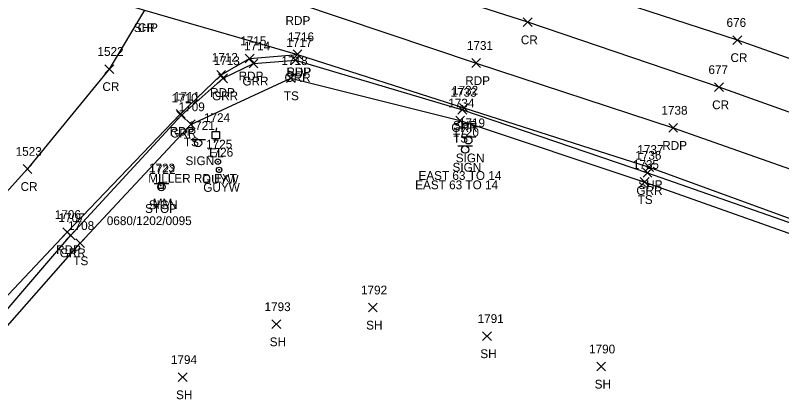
# Model space of a CAD drawing. Extents: x 1629176 to 1637209, y 606063 to 610167.
# Drawn here: x 1629900.9 to 1630075.4, y 606839.8 to 606927.3 of the extents above; entities that cross this region are included whole.
import ezdxf

# ---------------------------------------------------------------- set-up
doc = ezdxf.new("R2010")
doc.units = 0
for name, color, linetype in [('L_A', 7, 'Continuous'), ('L_I', 7, 'Continuous'), ('L_TIC', 7, 'Continuous'), ('LELB', 7, 'Continuous'), ('P_A', 7, 'Continuous'), ('P_I', 7, 'Continuous'), ('P_TIC', 7, 'Continuous'), ('PET', 7, 'Continuous'), ('PRC', 7, 'Continuous'), ('PSP', 7, 'Continuous'), ('R_A', 7, 'Continuous'), ('R_I', 7, 'Continuous'), ('R_TIC', 7, 'Continuous'), ('RGR', 7, 'Continuous'), ('S_A', 7, 'Continuous'), ('S_C', 7, 'Continuous'), ('S_I', 7, 'Continuous'), ('SRM', 7, 'Continuous'), ('SSGN', 7, 'Continuous'), ('U_A', 7, 'Continuous'), ('U_I', 7, 'Continuous'), ('UEPT', 7, 'Continuous'), ('UPGW', 7, 'Continuous')]:
    doc.layers.add(name, color=color, linetype=linetype)

msp = doc.modelspace()

# ---------------------------------------------------------------- linework, layer by layer
at = {"layer": 'L_TIC'}
for points in [[(1629962.67, 606911.99), (1629964.67, 606913.99)], [(1629964.67, 606911.99), (1629962.67, 606913.99)], [(1629939.9, 606901.48), (1629941.9, 606903.48)], [(1629941.9, 606901.48), (1629939.9, 606903.48)], [(1630001.21, 606902.33), (1630003.21, 606904.33)], [(1630003.21, 606902.33), (1630001.21, 606904.33)], [(1630043.25, 606888.35), (1630045.25, 606890.35)], [(1630045.25, 606888.35), (1630043.25, 606890.35)], [(1629914.71, 606874.42), (1629916.71, 606876.42)], [(1629916.71, 606874.42), (1629914.71, 606876.42)], [(1629981.34, 606859.75), (1629983.34, 606861.75)], [(1629983.34, 606859.75), (1629981.34, 606861.75)], [(1629959.37, 606855.95), (1629961.37, 606857.95)], [(1629961.37, 606855.95), (1629959.37, 606857.95)], [(1630007.33, 606853.24), (1630009.33, 606855.24)], [(1630009.33, 606853.24), (1630007.33, 606855.24)], [(1630033.36, 606846.31), (1630035.36, 606848.31)], [(1630035.36, 606846.31), (1630033.36, 606848.31)], [(1629938.04, 606843.89), (1629940.04, 606845.89)], [(1629940.04, 606843.89), (1629938.04, 606845.89)]]:
    msp.add_lwpolyline(points, dxfattribs=at)
at = {"layer": 'LELB'}
msp.add_lwpolyline([(1630072.99, 606627.47), (1630041.99, 606654.51), (1630010.01, 606681.22), (1629981.64, 606706.28), (1629935.83, 606746.98), (1629900.42, 606776.48), (1629884.89, 606790.02), (1629879.22, 606802.61), (1629877.3, 606811.37), (1629877.5, 606819.88), (1629880.93, 606830.79), (1629891.36, 606847.82), (1629915.71, 606875.42), (1629940.9, 606902.48), (1629963.67, 606912.99), (1630002.21, 606903.33), (1630044.25, 606889.35), (1630091.41, 606872.59)], dxfattribs=at)
at = {"layer": 'P_TIC'}
for points in [[(1630016.61, 606924.74), (1630018.61, 606926.74)], [(1630018.61, 606924.74), (1630016.61, 606926.74)], [(1630064.36, 606920.68), (1630066.36, 606922.68)], [(1630066.36, 606920.68), (1630064.36, 606922.68)], [(1629953.28, 606916.5), (1629955.28, 606918.5)], [(1629955.28, 606916.5), (1629953.28, 606918.5)], [(1629964.2, 606917.43), (1629966.2, 606919.43)], [(1629966.2, 606917.43), (1629964.2, 606919.43)], [(1629964.2, 606917.43), (1629966.2, 606919.43)], [(1629966.2, 606917.43), (1629964.2, 606919.43)], [(1630004.89, 606915.45), (1630006.89, 606917.45)], [(1630006.89, 606915.45), (1630004.89, 606917.45)], [(1629921.33, 606914.08), (1629923.33, 606916.08)], [(1629923.33, 606914.08), (1629921.33, 606916.08)], [(1629946.79, 606912.74), (1629948.79, 606914.74)], [(1629948.79, 606912.74), (1629946.79, 606914.74)], [(1630060.18, 606909.94), (1630062.18, 606911.94)], [(1630062.18, 606909.94), (1630060.18, 606911.94)], [(1630002.07, 606905.25), (1630004.07, 606907.25)], [(1630004.07, 606905.25), (1630002.07, 606907.25)], [(1629937.57, 606903.89), (1629939.57, 606905.89)], [(1629939.57, 606903.89), (1629937.57, 606905.89)], [(1630049.76, 606900.68), (1630051.76, 606902.68)], [(1630051.76, 606900.68), (1630049.76, 606902.68)], [(1629902.69, 606891.32), (1629904.69, 606893.32)], [(1629904.69, 606891.32), (1629902.69, 606893.32)], [(1630044.28, 606891.75), (1630046.28, 606893.75)], [(1630046.28, 606891.75), (1630044.28, 606893.75)], [(1629911.73, 606876.94), (1629913.73, 606878.94)], [(1629913.73, 606876.94), (1629911.73, 606878.94)]]:
    msp.add_lwpolyline(points, dxfattribs=at)
at = {"layer": 'PET'}
for points in [[(1629181.97, 607055.08), (1629220.58, 607054.17), (1629264.89, 607052.3), (1629300.55, 607050.62), (1629344.63, 607047.49), (1629382.7, 607044.36), (1629427.5, 607039.91), (1629466.96, 607035.43), (1629507.21, 607030.19), (1629538.75, 607025.9), (1629578.99, 607019.69), (1629624.23, 607012.05), (1629673.21, 607003.11), (1629718.04, 606993.87), (1629764.48, 606983.46), (1629805.04, 606973.93), (1629842.82, 606964.4), (1629884.8, 606953.15), (1629930.25, 606940.34), (1629964.97, 606930.13), (1630005.89, 606916.45), (1630050.76, 606901.68), (1630096.23, 606885.67)], [(1629587.14, 606776.73), (1629623.38, 606774.29), (1629651.95, 606774.51), (1629678.56, 606774.68), (1629701.14, 606776.11), (1629724.19, 606779.3), (1629746.4, 606783.99), (1629772.89, 606791.82), (1629808.22, 606801.42), (1629824.36, 606806.11), (1629835.79, 606810.93), (1629847.76, 606817.22), (1629860.47, 606825.17), (1629873.11, 606832.29), (1629887.14, 606850.82), (1629912.73, 606877.94), (1629938.57, 606904.89), (1629947.79, 606913.74), (1629954.28, 606917.5), (1629965.2, 606918.43)]]:
    msp.add_lwpolyline(points, dxfattribs=at)
at = {"layer": 'PRC'}
for points in [[(1630110.18, 606905.77), (1630065.36, 606921.68), (1630022.36, 606935.68), (1629994.71, 606945.36), (1629959.54, 606955.86), (1629913.54, 606969.37), (1629877.41, 606979.26), (1629837.69, 606989.99), (1629791.63, 607000.82), (1629746.42, 607011.44), (1629699.59, 607021.37), (1629664.04, 607028.34), (1629619.43, 607036.79), (1629585.72, 607042.18), (1629539.96, 607049.3), (1629491.45, 607056.02), (1629445.88, 607061.28), (1629404.36, 607066.23), (1629358.89, 607069.49), (1629314.63, 607073.29), (1629269.37, 607075.36), (1629226.58, 607077.32), (1629182.35, 607078.58)], [(1630105.99, 606894.95), (1630061.18, 606910.94), (1630017.61, 606925.74), (1629991.01, 606934.32), (1629955.3, 606944.84), (1629910.77, 606959.12), (1629874.52, 606969.06), (1629834.93, 606979.4), (1629788.74, 606990.13), (1629743.3, 607000.68), (1629697.98, 607010.33), (1629662.17, 607017.56), (1629618.2, 607025.81), (1629583.59, 607031.56), (1629540.4, 607037.95), (1629489.63, 607045.02), (1629444.26, 607050.14), (1629402.79, 607054.66), (1629359.1, 607058.26), (1629313.06, 607061.88), (1629268.47, 607063.97), (1629226.23, 607065.89), (1629182.22, 607066.96)], [(1629930.37, 606928.51), (1629922.33, 606915.08), (1629903.69, 606892.32), (1629888.42, 606875.5), (1629871.3, 606859.39), (1629850.1, 606843.52), (1629825.75, 606829.77), (1629796.32, 606815.42), (1629774.04, 606806.57), (1629748.19, 606798.61), (1629722.01, 606792.8), (1629693.98, 606789.27), (1629667.56, 606787.71), (1629632.27, 606787.81), (1629586.9, 606789.65)]]:
    msp.add_lwpolyline(points, dxfattribs=at)
at = {"layer": 'PSP'}
msp.add_lwpolyline([(1629181.26, 607044.82), (1629219.33, 607043.61), (1629263.7, 607041.6), (1629300.14, 607039.68), (1629342.49, 607036.76), (1629381.41, 607033.8), (1629425.61, 607029.43), (1629465.11, 607025.03), (1629505.36, 607019.79), (1629537.56, 607015.39), (1629576.08, 607009.38), (1629623.28, 607001.72), (1629671.03, 606992.73), (1629715.19, 606983.38), (1629761.23, 606973.52), (1629802.25, 606963.72), (1629839.3, 606954.1), (1629871.33, 606945.94), (1629930.37, 606928.51), (1629965.2, 606918.43), (1630003.07, 606906.25), (1630045.28, 606892.75), (1630092.08, 606875.64)], dxfattribs=at)
at = {"layer": 'R_TIC'}
for points in [[(1629954.15, 606915.34), (1629956.15, 606917.34)], [(1629956.15, 606915.34), (1629954.15, 606917.34)], [(1629963.74, 606916.13), (1629965.74, 606918.13)], [(1629965.74, 606916.13), (1629963.74, 606918.13)], [(1629947.22, 606911.98), (1629949.22, 606913.98)], [(1629949.22, 606911.98), (1629947.22, 606913.98)], [(1630001.73, 606904.78), (1630003.73, 606906.78)], [(1630003.73, 606904.78), (1630001.73, 606906.78)], [(1629937.73, 606903.49), (1629939.73, 606905.49)], [(1629939.73, 606903.49), (1629937.73, 606905.49)], [(1630043.87, 606890.43), (1630045.87, 606892.43)], [(1630045.87, 606890.43), (1630043.87, 606892.43)], [(1629912.53, 606876.22), (1629914.53, 606878.22)], [(1629914.53, 606876.22), (1629912.53, 606878.22)]]:
    msp.add_lwpolyline(points, dxfattribs=at)
at = {"layer": 'RGR'}
msp.add_lwpolyline([(1629883.56, 606789.68), (1629877.62, 606802.29), (1629875.27, 606811.1), (1629875.33, 606819.3), (1629879.52, 606832.4), (1629889.43, 606849.18), (1629913.53, 606877.22), (1629938.73, 606904.49), (1629948.22, 606912.98), (1629955.15, 606916.34), (1629964.74, 606917.13), (1630002.73, 606905.78), (1630044.87, 606891.43), (1630091.95, 606875)], dxfattribs=at)
at = {"layer": 'SRM'}
for p, q in [((1629934.68, 606889.2), (1629933.43, 606889.2)), ((1629933.43, 606889.2), (1629933.43, 606887.95)), ((1629934.68, 606889.2), (1629933.43, 606889.2)), ((1629933.43, 606889.2), (1629933.43, 606887.95)), ((1629934.68, 606887.95), (1629934.68, 606889.2)), ((1629934.68, 606887.95), (1629934.68, 606889.2)), ((1629933.43, 606887.95), (1629934.68, 606887.95)), ((1629933.43, 606887.95), (1629934.68, 606887.95))]:
    msp.add_line(p, q, dxfattribs=at)
msp.add_circle((1629934.03, 606888.54), 0.0833, dxfattribs=at)
at = {"layer": 'SSGN'}
for p, q in [((1630002.44, 606899.68), (1630005.78, 606899.68)), ((1629940.89, 606899.06), (1629944.22, 606899.06)), ((1629942.54, 606898.23), (1629942.54, 606898.23)), ((1630001.7, 606897.56), (1630005.04, 606897.56)), ((1630004.09, 606898.85), (1630004.09, 606898.85)), ((1630003.35, 606896.73), (1630003.35, 606896.73)), ((1629932.54, 606889.04), (1629935.87, 606889.04)), ((1629934.19, 606888.2), (1629934.19, 606888.2))]:
    msp.add_line(p, q, dxfattribs=at)
for centre in [(1630004.09, 606898.85), (1629942.54, 606898.23), (1630003.35, 606896.73), (1629934.19, 606888.2)]:
    msp.add_circle(centre, 0.833, dxfattribs=at)
at = {"layer": 'UEPT'}
for p, q in [((1629946.73, 606901.68), (1629946.56, 606900.85)), ((1629945.73, 606899.18), (1629945.73, 606900.85)), ((1629945.73, 606900.85), (1629947.4, 606900.85)), ((1629946.56, 606900.01), (1629946.56, 606900.01)), ((1629947.4, 606900.85), (1629947.4, 606899.18)), ((1629947.4, 606899.18), (1629945.73, 606899.18)), ((1629946.31, 606898.35), (1629946.56, 606899.18))]:
    msp.add_line(p, q, dxfattribs=at)
at = {"layer": 'UPGW'}
for centre, radius in [((1629947.06, 606893.98), 0.625), ((1629947.06, 606893.98), 0.0833), ((1629947.33, 606892.12), 0.625), ((1629947.33, 606892.12), 0.0833)]:
    msp.add_circle(centre, radius, dxfattribs=at)

# ---------------------------------------------------------------- texts
at = {"layer": 'L_A'}
for s, p in [('TS', (1629962.08, 606907.99)), ('TS', (1629939.31, 606897.48)), ('TS', (1630000.62, 606898.33)), ('TS', (1630042.66, 606884.35)), ('TS', (1629914.12, 606870.42)), ('SH', (1629980.82, 606855.75)), ('SH', (1629958.86, 606851.95)), ('SH', (1630006.82, 606849.24)), ('SH', (1630032.85, 606842.31)), ('SH', (1629937.53, 606839.89))]:
    msp.add_text(s, height=2, dxfattribs=at).set_placement(p)
at = {"layer": 'L_I'}
for s, p in [('1718', (1629961.54, 606915.99)), ('1734', (1629999.52, 606906.33)), ('1709', (1629938.12, 606905.48)), ('1735', (1630041.56, 606892.35)), ('1708', (1629912.94, 606878.42)), ('1792', (1629979.64, 606863.75)), ('1793', (1629957.68, 606859.95)), ('1791', (1630006.2, 606857.24)), ('1790', (1630031.58, 606850.31)), ('1794', (1629936.35, 606847.89))]:
    msp.add_text(s, height=2, dxfattribs=at).set_placement(p)
at = {"layer": 'P_A'}
for s, p in [('RDP', (1629962.46, 606925.13)), ('SHP', (1629927.9, 606923.51)), ('CR', (1629928.8, 606923.51)), ('CR', (1630016.05, 606920.74)), ('CR', (1630063.79, 606916.68)), ('SHP', (1629962.73, 606913.43)), ('RDP', (1629962.68, 606913.43)), ('RDP', (1629951.77, 606912.5)), ('RDP', (1630003.38, 606911.45)), ('CR', (1629920.76, 606910.08)), ('RDP', (1629945.28, 606908.74)), ('CR', (1630059.61, 606905.94)), ('SHP', (1630000.61, 606901.25)), ('RDP', (1629936.06, 606899.89)), ('RDP', (1630048.25, 606896.68)), ('CR', (1629902.12, 606887.32)), ('SHP', (1630042.81, 606887.75)), ('RDP', (1629910.22, 606872.94))]:
    msp.add_text(s, height=2, dxfattribs=at).set_placement(p)
at = {"layer": 'P_I'}
for s, p in [('676', (1630062.89, 606924.68)), ('1715', (1629952.15, 606920.5)), ('1716', (1629963.01, 606921.43)), ('1716', (1629963.01, 606921.43)), ('1731', (1630003.76, 606919.45)), ('1522', (1629919.63, 606918.08)), ('1712', (1629945.66, 606916.74)), ('677', (1630058.77, 606913.94)), ('1711', (1629937.01, 606907.89)), ('1732', (1630000.38, 606909.25)), ('1738', (1630048.06, 606904.68)), ('1737', (1630042.58, 606895.75)), ('1523', (1629901, 606895.32)), ('1706', (1629909.91, 606880.94))]:
    msp.add_text(s, height=2, dxfattribs=at).set_placement(p)
at = {"layer": 'R_A'}
for p in [(1629952.64, 606911.34), (1629962.23, 606912.13), (1629945.71, 606907.98), (1630000.22, 606900.78), (1629936.21, 606899.49), (1630042.36, 606886.43), (1629911.02, 606872.22)]:
    msp.add_text('GRR', height=2, dxfattribs=at).set_placement(p)
at = {"layer": 'R_I'}
for s, p in [('1717', (1629962.62, 606920.13)), ('1714', (1629953.02, 606919.34)), ('1713', (1629946.09, 606915.98)), ('1733', (1630000.04, 606908.78)), ('1710', (1629936.51, 606907.49)), ('1736', (1630042.12, 606894.43)), ('1707', (1629910.76, 606880.22))]:
    msp.add_text(s, height=2, dxfattribs=at).set_placement(p)
at = {"layer": 'S_A'}
for s, p in [('SIGN', (1630001.23, 606893.83)), ('SIGN', (1629939.67, 606893.2)), ('SIGN', (1630000.49, 606891.71)), ('MM', (1629932.22, 606883.54)), ('SIGN', (1629931.32, 606883.18))]:
    msp.add_text(s, height=2, dxfattribs=at).set_placement(p)
at = {"layer": 'S_C'}
for s, p in [('MILLER RD EXT', (1629931.19, 606889.2)), ('EAST 63 TO 14', (1629992.73, 606889.83)), ('EAST 63 TO 14', (1629991.99, 606887.71)), ('STOP', (1629930.47, 606882.31)), ('0680/1202/0095', (1629921.76, 606879.54))]:
    msp.add_text(s, height=2, dxfattribs=at).set_placement(p)
at = {"layer": 'S_I'}
for s, p in [('1721', (1629940.39, 606901.2)), ('1719', (1630001.94, 606901.83)), ('1720', (1630000.55, 606899.71)), ('1723', (1629931.34, 606891.54)), ('1722', (1629931.47, 606891.18))]:
    msp.add_text(s, height=2, dxfattribs=at).set_placement(p)
at = {"layer": 'U_A'}
for s, p in [('EL', (1629945.1, 606895.01)), ('GUYW', (1629943.45, 606888.98)), ('GUYW', (1629943.73, 606887.12))]:
    msp.add_text(s, height=2, dxfattribs=at).set_placement(p)
at = {"layer": 'U_I'}
for s, p in [('1724', (1629943.87, 606903.01)), ('1725', (1629944.37, 606896.98)), ('1726', (1629944.59, 606895.12))]:
    msp.add_text(s, height=2, dxfattribs=at).set_placement(p)

doc.saveas('drawing.dxf')
